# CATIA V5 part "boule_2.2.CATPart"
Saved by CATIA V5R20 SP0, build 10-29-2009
Part number: boule_2.2
Bounding box of the stored display mesh (mm): x 2784.952 to 2880.778, y -701.152 to -601.163, z -702.084 to -602.098
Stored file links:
  D:\thinkmotion-MPB\Dropbox\MMS_GR3\CFAO_2010_bfoltzer\CFAO_bfoltzer\boule_2.2.CATPart
  D:\ecole\thinkmotion\Eolienne.CATProduct
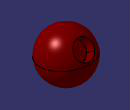
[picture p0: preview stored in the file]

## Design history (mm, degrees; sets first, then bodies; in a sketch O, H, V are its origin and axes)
External parameters (linked from other documents)
  External.rayon_barre = 20 mm
Set1
  Plane1: linked copy from another document
  Point1 to Point3: linked copy from another document
  Line1: linked copy from another document
  Point4: linked copy from another document
  Plane2: linked copy from another document
  Plane3: linked copy from another document
Body1 (main body)
  Sketch1 on Plane1, origin (0, 73.0349, -126.3664), H (-1, 0, 0), V (0, 0.8092, 0.5875)
    arc A1 centre (-2830.7782, -894.8969) radius 50 from (-2780.7782, -894.8969) to (-2880.7782, -894.8969) ccw
    point P1 (-2830.7782, -894.8969)
    point P2 (-2780.7782, -894.8969)
    point P3 (-2880.7782, -894.8969)
    reference projected point E1 (-2880.7782, -894.8969) from Point1
    reference projected point E2 (-2780.7782, -894.8969) from Point2
    reference projected point E3 (-2830.7782, -894.8969) from Point3
    coincidence: P3 E1, P2 E2, P1 E3
  Shaft1: profile Sketch1, axis Line1, angle 360
  Sketch2 on {plane type Tangent, Support face of Shaft1 from Sketch1.A1, RefPoint Point4}, origin (2830.7782, -1703.4174, 882.5215), H (1, 0, 0), V (0, -0.5875, 0.8092)
    point P1 (0, -1860.0502)
    reference projected point E1 (0, -1860.0502) from Point4
    coincidence: E1 P1
  Hole1: placed by Sketch2, at (2830.7782, -610.6949, -622.7175) direction (0, -0.8092, -0.5875), diameter 40 {= External.rayon_barre *2}, up to Plane2
  Sketch3 on {plane type Tangent, Support face of Shaft1 from Sketch1.A1, RefPoint Point2}, origin (2780.7782, -966.2417, -546.3305), H (0, 1, 0), V (0, 0, 1)
    point P1 (315.0844, -105.7605)
    reference projected point E1 (315.0844, -105.7605) from Point2
    coincidence: E1 P1
  Hole2: placed by Sketch3, at (2780.7782, -651.1573, -652.091) direction (1, 0, 0), diameter 40 {= External.rayon_barre *2}, up to Plane3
